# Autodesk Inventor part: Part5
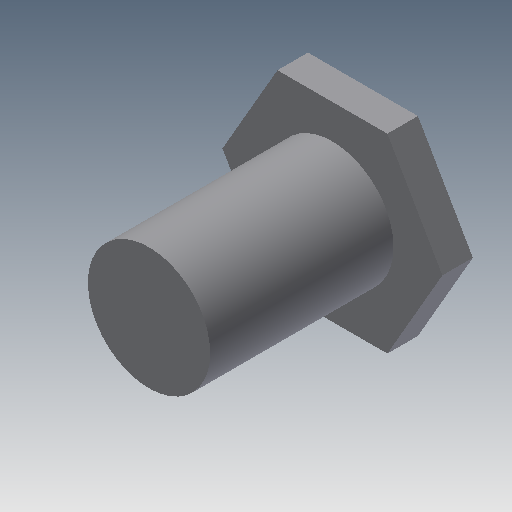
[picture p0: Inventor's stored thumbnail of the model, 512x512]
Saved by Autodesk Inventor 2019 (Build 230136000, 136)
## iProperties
Created: 2008-05
Part Number: Part5
Document SubType Name: Modeling
Designer: CADCIM
Density: 1 g/cm^3
Material: Generic
Appearance: Default
Author: CADCIM
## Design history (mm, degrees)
sketch "Sketch1"
  geometry: C1 r 2 at (-7.12, 11.618)
  constraints: 1 centre point
  dimensions: "d2" = 4 diameter of C1
extrude "Extrusion1" new body sketch "Sketch1" distance "d0" = 6; taper "d1" = 0 deg
sketch "Sketch2"
  geometry: L1 (-3.598, 0)-(-1.799, 3.116); L2 (-1.799, 3.116)-(1.799, 3.116); L3 (1.799, 3.116)-(3.598, 0); L4 (3.598, 0)-(1.799, -3.116); L5 (1.799, -3.116)-(-1.799, -3.116); L6 (-1.799, -3.116)-(-3.598, 0); C1 r 2 at (0, 0) reference; 1 further point
  constraints: 12 end point, 1 coincident, 13 other
extrude "Extrusion2" join sketch "Sketch2" distance "d3" = 1; taper "d4" = 0 deg
body "Solid1"
